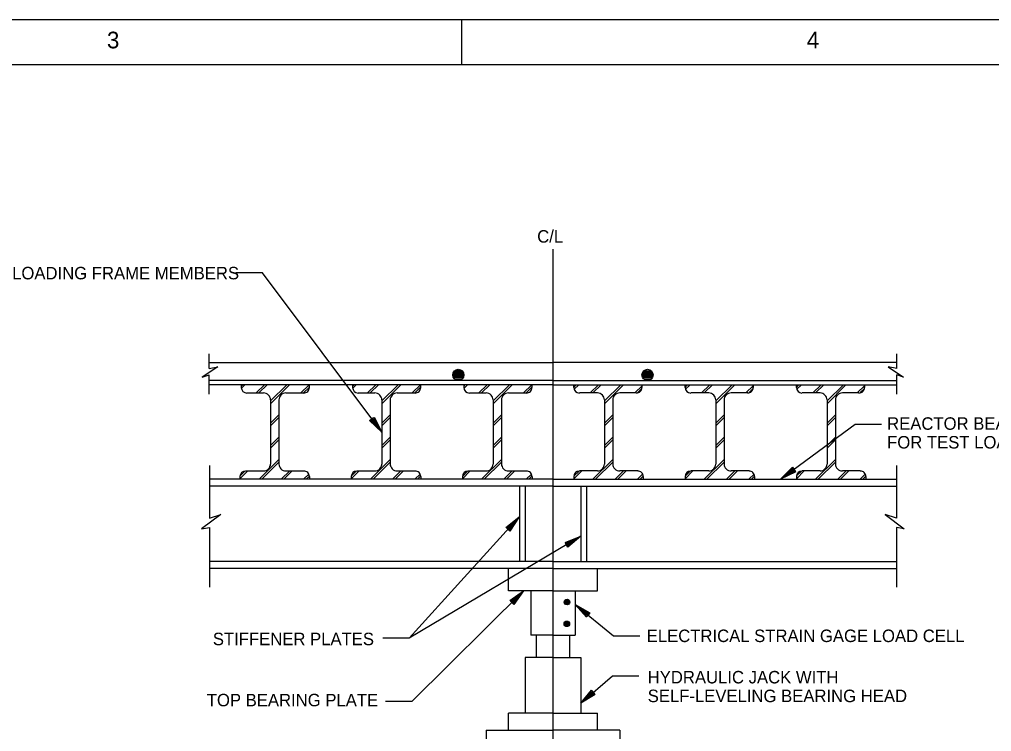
# Model space of a CAD drawing. Extents: x 22378.6 to 22422.6, y 22377.7 to 22411.7.
# Drawn here: x 22398.72 to 22409.64, y 22403.67 to 22411.66 of the extents above; entities that cross this region are included whole.
import ezdxf

# ---------------------------------------------------------------- set-up
doc = ezdxf.new("R2010")
doc.units = 0
for name, color, linetype in [('Level 1', 7, 'Continuous'), ('Level 10', 7, 'Continuous'), ('Level 2', 7, 'Continuous'), ('Level 4', 7, 'Continuous'), ('Level 7', 7, 'Continuous'), ('Level 9', 7, 'Continuous')]:
    doc.layers.add(name, color=color, linetype=linetype)

msp = doc.modelspace()

# ---------------------------------------------------------------- linework, layer by layer
at = {"layer": 'Level 1'}
for p, q in [((22404.71, 22409.083), (22404.71, 22399.845)), ((22400.847, 22407.741), (22400.847, 22407.909)), ((22408.573, 22407.741), (22408.573, 22407.909)), ((22400.947, 22407.761), (22400.772, 22407.644)), ((22400.847, 22407.741), (22400.947, 22407.761)), ((22408.573, 22407.741), (22408.473, 22407.761)), ((22408.473, 22407.761), (22408.648, 22407.644)), ((22400.772, 22407.644), (22400.847, 22407.672)), ((22400.847, 22407.455), (22400.847, 22407.672)), ((22408.573, 22407.455), (22408.573, 22407.672)), ((22408.648, 22407.644), (22408.573, 22407.672)), ((22401.21, 22407.55), (22401.222, 22407.561)), ((22401.211, 22407.521), (22401.251, 22407.561)), ((22401.378, 22407.468), (22401.472, 22407.561)), ((22401.408, 22407.468), (22401.501, 22407.561)), ((22401.538, 22407.378), (22401.722, 22407.561)), ((22401.538, 22407.348), (22401.751, 22407.561)), ((22401.878, 22407.468), (22401.972, 22407.561)), ((22402.46, 22407.55), (22402.472, 22407.561)), ((22402.461, 22407.521), (22402.501, 22407.561)), ((22402.628, 22407.468), (22402.722, 22407.561)), ((22402.657, 22407.468), (22402.751, 22407.561)), ((22402.788, 22407.378), (22402.972, 22407.561)), ((22402.788, 22407.348), (22403.001, 22407.561)), ((22403.128, 22407.468), (22403.222, 22407.561)), ((22403.157, 22407.468), (22403.226, 22407.536)), ((22403.711, 22407.522), (22403.751, 22407.561)), ((22403.711, 22407.55), (22403.722, 22407.561)), ((22403.878, 22407.468), (22403.972, 22407.561)), ((22403.907, 22407.468), (22404.001, 22407.561)), ((22404.038, 22407.378), (22404.222, 22407.561)), ((22404.038, 22407.348), (22404.251, 22407.561)), ((22404.378, 22407.468), (22404.472, 22407.561)), ((22404.408, 22407.468), (22404.475, 22407.536)), ((22404.945, 22407.535), (22404.972, 22407.561)), ((22404.949, 22407.509), (22405.001, 22407.561)), ((22405.128, 22407.468), (22405.222, 22407.561)), ((22405.157, 22407.468), (22405.251, 22407.561)), ((22405.288, 22407.378), (22405.472, 22407.561)), ((22405.288, 22407.348), (22405.501, 22407.561)), ((22405.628, 22407.468), (22405.711, 22407.55)), ((22406.195, 22407.535), (22406.222, 22407.561)), ((22406.199, 22407.509), (22406.251, 22407.561)), ((22406.378, 22407.468), (22406.472, 22407.561)), ((22406.407, 22407.468), (22406.501, 22407.561)), ((22406.538, 22407.378), (22406.722, 22407.561)), ((22406.538, 22407.348), (22406.751, 22407.561)), ((22406.878, 22407.468), (22406.96, 22407.55)), ((22407.445, 22407.535), (22407.472, 22407.561)), ((22407.449, 22407.51), (22407.501, 22407.561)), ((22407.628, 22407.468), (22407.722, 22407.561)), ((22407.658, 22407.468), (22407.751, 22407.561)), ((22407.788, 22407.378), (22407.972, 22407.561)), ((22407.788, 22407.348), (22408.001, 22407.561)), ((22408.128, 22407.468), (22408.21, 22407.55)), ((22401.907, 22407.468), (22401.974, 22407.535)), ((22405.66, 22407.47), (22405.706, 22407.516)), ((22406.911, 22407.471), (22406.957, 22407.518)), ((22408.161, 22407.472), (22408.208, 22407.519)), ((22401.538, 22407.128), (22401.632, 22407.222)), ((22402.788, 22407.128), (22402.882, 22407.222)), ((22404.038, 22407.128), (22404.132, 22407.222)), ((22405.288, 22407.128), (22405.382, 22407.222)), ((22406.538, 22407.128), (22406.632, 22407.222)), ((22407.788, 22407.128), (22407.882, 22407.222)), ((22401.538, 22407.098), (22401.632, 22407.192)), ((22402.788, 22407.098), (22402.882, 22407.192)), ((22404.038, 22407.098), (22404.132, 22407.192)), ((22405.288, 22407.098), (22405.382, 22407.192)), ((22406.538, 22407.098), (22406.632, 22407.192)), ((22407.788, 22407.098), (22407.882, 22407.192)), ((22402.757, 22407.07), (22402.757, 22407.07)), ((22402.788, 22407.028), (22402.788, 22407.028)), ((22401.538, 22406.878), (22401.632, 22406.972)), ((22401.538, 22406.848), (22401.632, 22406.942)), ((22402.788, 22406.878), (22402.882, 22406.972)), ((22402.788, 22406.848), (22402.882, 22406.942)), ((22404.038, 22406.878), (22404.132, 22406.972)), ((22404.038, 22406.848), (22404.132, 22406.942)), ((22405.288, 22406.878), (22405.382, 22406.972)), ((22405.288, 22406.848), (22405.382, 22406.942)), ((22406.538, 22406.878), (22406.632, 22406.972)), ((22406.538, 22406.848), (22406.632, 22406.942)), ((22407.788, 22406.878), (22407.882, 22406.972)), ((22407.788, 22406.848), (22407.882, 22406.942)), ((22401.409, 22406.499), (22401.632, 22406.722)), ((22401.439, 22406.499), (22401.632, 22406.692)), ((22402.659, 22406.499), (22402.882, 22406.722)), ((22402.689, 22406.499), (22402.882, 22406.692)), ((22403.909, 22406.499), (22404.132, 22406.722)), ((22403.939, 22406.499), (22404.132, 22406.692)), ((22405.159, 22406.499), (22405.382, 22406.722)), ((22405.189, 22406.499), (22405.382, 22406.692)), ((22406.409, 22406.499), (22406.632, 22406.722)), ((22406.439, 22406.499), (22406.632, 22406.692)), ((22407.659, 22406.499), (22407.882, 22406.722)), ((22407.689, 22406.499), (22407.882, 22406.692)), ((22400.851, 22406.655), (22400.851, 22406.062)), ((22401.195, 22406.505), (22401.282, 22406.593)), ((22401.195, 22406.535), (22401.251, 22406.591)), ((22401.659, 22406.499), (22401.753, 22406.593)), ((22401.689, 22406.499), (22401.782, 22406.593)), ((22401.909, 22406.499), (22401.967, 22406.557)), ((22402.445, 22406.505), (22402.532, 22406.593)), ((22402.447, 22406.537), (22402.5, 22406.59)), ((22402.909, 22406.499), (22403.003, 22406.593)), ((22402.939, 22406.499), (22403.032, 22406.593)), ((22403.159, 22406.499), (22403.218, 22406.558)), ((22403.695, 22406.505), (22403.782, 22406.593)), ((22403.696, 22406.536), (22403.753, 22406.593)), ((22404.159, 22406.499), (22404.253, 22406.593)), ((22404.189, 22406.499), (22404.282, 22406.593)), ((22404.409, 22406.499), (22404.468, 22406.557)), ((22404.945, 22406.505), (22405.033, 22406.593)), ((22404.946, 22406.535), (22405.003, 22406.592)), ((22405.409, 22406.499), (22405.503, 22406.593)), ((22405.439, 22406.499), (22405.533, 22406.593)), ((22405.659, 22406.499), (22405.717, 22406.557)), ((22406.195, 22406.505), (22406.282, 22406.593)), ((22406.195, 22406.534), (22406.252, 22406.592)), ((22406.659, 22406.499), (22406.753, 22406.593)), ((22406.689, 22406.499), (22406.782, 22406.593)), ((22406.909, 22406.499), (22406.968, 22406.558)), ((22407.445, 22406.505), (22407.532, 22406.593)), ((22407.447, 22406.537), (22407.501, 22406.591)), ((22407.909, 22406.499), (22408.003, 22406.593)), ((22407.939, 22406.499), (22408.032, 22406.593)), ((22408.159, 22406.499), (22408.218, 22406.557)), ((22408.569, 22406.655), (22408.569, 22406.062)), ((22401.939, 22406.499), (22401.974, 22406.534)), ((22403.189, 22406.499), (22403.224, 22406.534)), ((22404.439, 22406.499), (22404.473, 22406.534)), ((22405.689, 22406.499), (22405.725, 22406.535)), ((22406.939, 22406.499), (22406.975, 22406.535)), ((22407.267, 22406.499), (22407.267, 22406.499)), ((22407.309, 22406.53), (22407.309, 22406.53)), ((22408.189, 22406.499), (22408.224, 22406.535)), ((22400.98, 22406.105), (22400.764, 22405.942)), ((22400.851, 22406.062), (22400.98, 22406.105)), ((22403.095, 22404.715), (22404.329, 22406.078)), ((22404.294, 22406.039), (22404.294, 22406.039)), ((22404.329, 22406.078), (22404.329, 22406.078)), ((22408.44, 22406.105), (22408.656, 22405.942)), ((22408.569, 22406.062), (22408.44, 22406.105)), ((22400.764, 22405.942), (22400.851, 22405.96)), ((22400.851, 22405.96), (22400.851, 22405.288)), ((22408.569, 22405.96), (22408.569, 22405.288)), ((22408.656, 22405.942), (22408.569, 22405.96)), ((22404.978, 22405.835), (22404.978, 22405.835)), ((22405.022, 22405.861), (22405.022, 22405.861)), ((22404.381, 22405.249), (22404.381, 22405.249)), ((22404.344, 22405.212), (22404.344, 22405.212)), ((22404.96, 22405.095), (22404.96, 22405.095)), ((22405, 22405.062), (22405, 22405.062)), ((22405.022, 22403.987), (22405.022, 22403.987)), ((22405.062, 22404.021), (22405.062, 22404.021))]:
    msp.add_line(p, q, dxfattribs=at)
msp.add_lwpolyline([(22378.629, 22411.659), (22422.645, 22411.659), (22422.645, 22377.651), (22378.629, 22377.651)], close=True, dxfattribs=at)
for points in [[(22402.788, 22407.028), (22401.446, 22408.816), (22401.149, 22408.816)], [(22402.701, 22407.196), (22402.788, 22407.028), (22402.651, 22407.159), (22402.693, 22407.191), (22402.757, 22407.07), (22402.664, 22407.159), (22402.691, 22407.179), (22402.727, 22407.11), (22402.677, 22407.158), (22402.688, 22407.167), (22402.696, 22407.151)], [(22407.267, 22406.499), (22408.104, 22407.118), (22408.4, 22407.118)], [(22407.436, 22406.585), (22407.267, 22406.499), (22407.399, 22406.635), (22407.431, 22406.592), (22407.309, 22406.53), (22407.399, 22406.622), (22407.419, 22406.595), (22407.349, 22406.56), (22407.398, 22406.609), (22407.407, 22406.598), (22407.391, 22406.591)], [(22404.181, 22405.96), (22404.329, 22406.078), (22404.227, 22405.918), (22404.188, 22405.954), (22404.294, 22406.039), (22404.225, 22405.931), (22404.2, 22405.954), (22404.261, 22406.002), (22404.223, 22405.943), (22404.212, 22405.953), (22404.226, 22405.963)], [(22405.022, 22405.861), (22403.095, 22404.715), (22402.799, 22404.715)], [(22404.846, 22405.792), (22405.022, 22405.861), (22404.878, 22405.739), (22404.85, 22405.784), (22404.978, 22405.835), (22404.879, 22405.752), (22404.862, 22405.781), (22404.935, 22405.809), (22404.881, 22405.764), (22404.874, 22405.776), (22404.89, 22405.782)], [(22404.381, 22405.249), (22403.125, 22404.007), (22402.829, 22404.007)], [(22404.226, 22405.139), (22404.381, 22405.249), (22404.269, 22405.095), (22404.232, 22405.133), (22404.344, 22405.212), (22404.268, 22405.108), (22404.244, 22405.132), (22404.308, 22405.177), (22404.267, 22405.121), (22404.257, 22405.131), (22404.271, 22405.141)], [(22404.96, 22405.095), (22405.391, 22404.744), (22405.687, 22404.744)], [(22405.085, 22404.952), (22404.96, 22405.095), (22405.124, 22405), (22405.091, 22404.959), (22405, 22405.062), (22405.112, 22404.998), (22405.09, 22404.971), (22405.039, 22405.03), (22405.099, 22404.995), (22405.091, 22404.984), (22405.079, 22404.997)], [(22405.022, 22403.987), (22405.378, 22404.293), (22405.674, 22404.293)], [(22405.184, 22404.086), (22405.022, 22403.987), (22405.144, 22404.133), (22405.179, 22404.092), (22405.062, 22404.021), (22405.144, 22404.12), (22405.167, 22404.094), (22405.1, 22404.054), (22405.145, 22404.107), (22405.154, 22404.096), (22405.139, 22404.088)]]:
    msp.add_lwpolyline(points, dxfattribs=at)
at = {"layer": 'Level 10'}
msp.add_line((22403.685, 22411.155), (22403.685, 22411.659), dxfattribs=at)
at = {"layer": 'Level 2'}
for p, q in [((22400.847, 22407.811), (22404.71, 22407.811)), ((22408.573, 22407.811), (22404.71, 22407.811)), ((22403.71, 22407.671), (22403.586, 22407.671)), ((22403.707, 22407.687), (22403.589, 22407.687)), ((22403.707, 22407.655), (22403.589, 22407.655)), ((22403.7, 22407.702), (22403.595, 22407.702)), ((22403.689, 22407.718), (22403.608, 22407.718)), ((22405.709, 22407.671), (22405.834, 22407.671)), ((22405.713, 22407.687), (22405.831, 22407.687)), ((22405.713, 22407.655), (22405.831, 22407.655)), ((22405.72, 22407.702), (22405.825, 22407.702)), ((22405.731, 22407.718), (22405.811, 22407.718)), ((22404.71, 22407.608), (22400.847, 22407.608)), ((22404.71, 22407.561), (22400.847, 22407.561)), ((22401.21, 22407.561), (22401.21, 22407.53)), ((22401.975, 22407.53), (22401.975, 22407.561)), ((22402.46, 22407.561), (22402.46, 22407.53)), ((22403.225, 22407.53), (22403.225, 22407.561)), ((22403.702, 22407.64), (22403.593, 22407.64)), ((22403.686, 22407.624), (22403.605, 22407.624)), ((22403.71, 22407.561), (22403.71, 22407.53)), ((22404.475, 22407.53), (22404.475, 22407.561)), ((22404.71, 22407.608), (22408.573, 22407.608)), ((22404.71, 22407.561), (22408.573, 22407.561)), ((22404.945, 22407.53), (22404.945, 22407.561)), ((22405.71, 22407.561), (22405.71, 22407.53)), ((22405.718, 22407.64), (22405.827, 22407.64)), ((22405.734, 22407.624), (22405.815, 22407.624)), ((22406.195, 22407.53), (22406.195, 22407.561)), ((22406.96, 22407.561), (22406.96, 22407.53)), ((22407.445, 22407.53), (22407.445, 22407.561)), ((22408.21, 22407.561), (22408.21, 22407.53)), ((22401.272, 22407.468), (22401.46, 22407.468)), ((22401.71, 22407.468), (22401.912, 22407.468)), ((22402.522, 22407.468), (22402.71, 22407.468)), ((22402.96, 22407.468), (22403.162, 22407.468)), ((22403.772, 22407.468), (22403.96, 22407.468)), ((22404.21, 22407.468), (22404.412, 22407.468)), ((22405.21, 22407.468), (22405.007, 22407.468)), ((22405.647, 22407.468), (22405.46, 22407.468)), ((22406.46, 22407.468), (22406.257, 22407.468)), ((22406.897, 22407.468), (22406.71, 22407.468)), ((22407.71, 22407.468), (22407.507, 22407.468)), ((22408.147, 22407.468), (22407.96, 22407.468)), ((22401.538, 22407.39), (22401.538, 22406.671)), ((22401.632, 22407.39), (22401.632, 22406.671)), ((22402.788, 22407.39), (22402.788, 22406.671)), ((22402.882, 22407.39), (22402.882, 22406.671)), ((22404.038, 22407.39), (22404.038, 22406.671)), ((22404.132, 22407.39), (22404.132, 22406.671)), ((22405.288, 22407.39), (22405.288, 22406.671)), ((22405.382, 22407.39), (22405.382, 22406.671)), ((22406.538, 22407.39), (22406.538, 22406.671)), ((22406.632, 22407.39), (22406.632, 22406.671)), ((22407.788, 22407.39), (22407.788, 22406.671)), ((22407.882, 22407.39), (22407.882, 22406.671)), ((22401.257, 22406.593), (22401.46, 22406.593)), ((22401.71, 22406.593), (22401.912, 22406.593)), ((22402.507, 22406.593), (22402.71, 22406.593)), ((22402.96, 22406.593), (22403.162, 22406.593)), ((22403.757, 22406.593), (22403.96, 22406.593)), ((22404.21, 22406.593), (22404.412, 22406.593)), ((22405.21, 22406.593), (22405.007, 22406.593)), ((22405.662, 22406.593), (22405.46, 22406.593)), ((22406.46, 22406.593), (22406.257, 22406.593)), ((22406.912, 22406.593), (22406.71, 22406.593)), ((22407.71, 22406.593), (22407.507, 22406.593)), ((22408.162, 22406.593), (22407.96, 22406.593)), ((22401.195, 22406.53), (22401.195, 22406.499)), ((22401.975, 22406.53), (22401.975, 22406.499)), ((22402.445, 22406.53), (22402.445, 22406.499)), ((22403.225, 22406.53), (22403.225, 22406.499)), ((22403.695, 22406.53), (22403.695, 22406.499)), ((22404.475, 22406.53), (22404.475, 22406.499)), ((22404.945, 22406.53), (22404.945, 22406.499)), ((22405.725, 22406.53), (22405.725, 22406.499)), ((22406.195, 22406.53), (22406.195, 22406.499)), ((22406.975, 22406.53), (22406.975, 22406.499)), ((22407.445, 22406.53), (22407.445, 22406.499)), ((22408.225, 22406.53), (22408.225, 22406.499)), ((22404.335, 22406.421), (22404.335, 22405.577)), ((22404.397, 22406.421), (22404.397, 22405.577)), ((22405.022, 22406.421), (22405.022, 22405.577)), ((22405.085, 22406.421), (22405.085, 22405.577)), ((22404.891, 22405.144), (22404.844, 22405.144)), ((22404.895, 22405.112), (22404.835, 22405.112)), ((22404.899, 22405.128), (22404.84, 22405.128)), ((22404.889, 22405.097), (22404.848, 22405.097)), ((22404.896, 22404.878), (22404.833, 22404.878)), ((22404.892, 22404.863), (22404.84, 22404.863)), ((22404.89, 22404.894), (22404.842, 22404.894))]:
    msp.add_line(p, q, dxfattribs=at)
for centre, radius in [((22403.647, 22407.671), 0.0625), ((22405.772, 22407.671), 0.0625), ((22404.868, 22405.122), 0.0312), ((22404.866, 22404.878), 0.0312)]:
    msp.add_circle(centre, radius, dxfattribs=at)
for centre, radius, start, end in [((22401.272, 22407.53), 0.0625, 180.0046, 269.9954), ((22401.46, 22407.39), 0.078, 359.9952, 90.0048), ((22401.71, 22407.39), 0.078, 89.9952, 180.0048), ((22401.912, 22407.53), 0.0625, 269.9883, 0.0117), ((22402.522, 22407.53), 0.0625, 180.0046, 269.9954), ((22402.71, 22407.39), 0.078, 359.9952, 90.0048), ((22402.96, 22407.39), 0.078, 89.9952, 180.0048), ((22403.162, 22407.53), 0.0625, 269.9883, 0.0117), ((22403.772, 22407.53), 0.0625, 180.0046, 269.9954), ((22403.96, 22407.39), 0.078, 359.9952, 90.0048), ((22404.21, 22407.39), 0.078, 89.9952, 180.0048), ((22404.412, 22407.53), 0.0625, 269.9883, 0.0117), ((22405.007, 22407.53), 0.0625, 180.0046, 269.9954), ((22405.21, 22407.39), 0.078, 359.9952, 90.0048), ((22405.46, 22407.39), 0.078, 89.9952, 180.0048), ((22405.647, 22407.53), 0.0625, 269.9883, 0.0117), ((22406.257, 22407.53), 0.0625, 180.0046, 269.9954), ((22406.46, 22407.39), 0.078, 359.9952, 90.0048), ((22406.71, 22407.39), 0.078, 89.9952, 180.0048), ((22406.897, 22407.53), 0.0625, 269.9883, 0.0117), ((22407.507, 22407.53), 0.0625, 180.0046, 269.9954), ((22407.71, 22407.39), 0.078, 359.9952, 90.0048), ((22407.96, 22407.39), 0.078, 89.9952, 180.0048), ((22408.147, 22407.53), 0.0625, 269.9883, 0.0117), ((22401.46, 22406.671), 0.078, 269.9952, 0.0048), ((22401.71, 22406.671), 0.078, 179.9952, 270.0048), ((22402.71, 22406.671), 0.078, 269.9952, 0.0048), ((22402.96, 22406.671), 0.078, 179.9952, 270.0048), ((22403.96, 22406.671), 0.078, 269.9952, 0.0048), ((22404.21, 22406.671), 0.078, 179.9952, 270.0048), ((22405.21, 22406.671), 0.078, 269.9952, 0.0048), ((22405.46, 22406.671), 0.078, 179.9952, 270.0048), ((22406.46, 22406.671), 0.078, 269.9952, 0.0048), ((22406.71, 22406.671), 0.078, 179.9952, 270.0048), ((22407.71, 22406.671), 0.078, 269.9952, 0.0048), ((22407.96, 22406.671), 0.078, 179.9952, 270.0048), ((22401.257, 22406.53), 0.0625, 90.0046, 179.9954), ((22401.912, 22406.53), 0.0625, 359.9883, 90.0117), ((22402.507, 22406.53), 0.0625, 90.0046, 179.9954), ((22403.162, 22406.53), 0.0625, 359.9883, 90.0117), ((22403.757, 22406.53), 0.0625, 90.0046, 179.9954), ((22404.412, 22406.53), 0.0625, 359.9883, 90.0117), ((22405.007, 22406.53), 0.0625, 90.0046, 179.9954), ((22405.662, 22406.53), 0.0625, 359.9883, 90.0117), ((22406.257, 22406.53), 0.0625, 90.0046, 179.9954), ((22406.912, 22406.53), 0.0625, 359.9883, 90.0117), ((22407.507, 22406.53), 0.0625, 90.0046, 179.9954), ((22408.162, 22406.53), 0.0625, 359.9883, 90.0117)]:
    msp.add_arc(centre, radius, start, end, dxfattribs=at)
at = {"layer": 'Level 7'}
for p, q in [((22404.71, 22406.499), (22400.851, 22406.499)), ((22404.71, 22406.499), (22408.569, 22406.499)), ((22404.71, 22406.421), (22400.851, 22406.421)), ((22404.71, 22406.421), (22408.569, 22406.421)), ((22404.71, 22405.577), (22400.851, 22405.577)), ((22404.71, 22405.577), (22408.569, 22405.577)), ((22404.71, 22405.499), (22400.851, 22405.499)), ((22404.21, 22405.249), (22404.21, 22405.499)), ((22404.71, 22405.499), (22408.569, 22405.499)), ((22405.21, 22405.249), (22405.21, 22405.499)), ((22404.71, 22405.249), (22404.21, 22405.249)), ((22404.46, 22405.249), (22404.46, 22404.749)), ((22404.71, 22405.249), (22405.21, 22405.249)), ((22404.96, 22405.249), (22404.96, 22404.749)), ((22404.71, 22404.749), (22404.46, 22404.749)), ((22404.522, 22404.749), (22404.522, 22404.499)), ((22404.71, 22404.749), (22404.96, 22404.749)), ((22404.897, 22404.749), (22404.897, 22404.499)), ((22404.71, 22404.499), (22404.397, 22404.499)), ((22404.397, 22404.499), (22404.397, 22403.874)), ((22404.71, 22404.499), (22405.022, 22404.499)), ((22405.022, 22404.499), (22405.022, 22403.874)), ((22404.71, 22403.874), (22404.21, 22403.874)), ((22404.21, 22403.686), (22404.21, 22403.874)), ((22404.71, 22403.874), (22405.21, 22403.874)), ((22405.21, 22403.686), (22405.21, 22403.874)), ((22403.96, 22403.686), (22404.71, 22403.686)), ((22403.96, 22403.686), (22403.96, 22403.436)), ((22405.46, 22403.686), (22404.71, 22403.686)), ((22405.46, 22403.686), (22405.46, 22403.436))]:
    msp.add_line(p, q, dxfattribs=at)
at = {"layer": 'Level 9'}
msp.add_line((22380.129, 22411.155), (22419.393, 22411.155), dxfattribs=at)

# ---------------------------------------------------------------- texts
at = {"layer": 'Level 1'}
for s, p in [('3', (22399.701, 22411.335)), ('4', (22407.561, 22411.335))]:
    msp.add_text(s, height=0.187, dxfattribs=at).set_placement(p)
at = {"layer": 'Level 4'}
for s, p in [('C/L', (22404.533, 22409.155)), ('LOADING FRAME MEMBERS', (22398.636, 22408.743)), ('REACTOR BEAMS ', (22408.463, 22407.055)), ('FOR TEST LOAD', (22408.463, 22406.845)), ('ELECTRICAL STRAIN GAGE LOAD CELL', (22405.763, 22404.673)), ('STIFFENER PLATES', (22400.89, 22404.638)), ('HYDRAULIC JACK WITH', (22405.774, 22404.209)), ('TOP BEARING PLATE', (22400.822, 22403.952)), ('SELF-LEVELING BEARING HEAD', (22405.774, 22403.999))]:
    msp.add_text(s, height=0.14, dxfattribs=at).set_placement(p)

doc.saveas('drawing.dxf')
